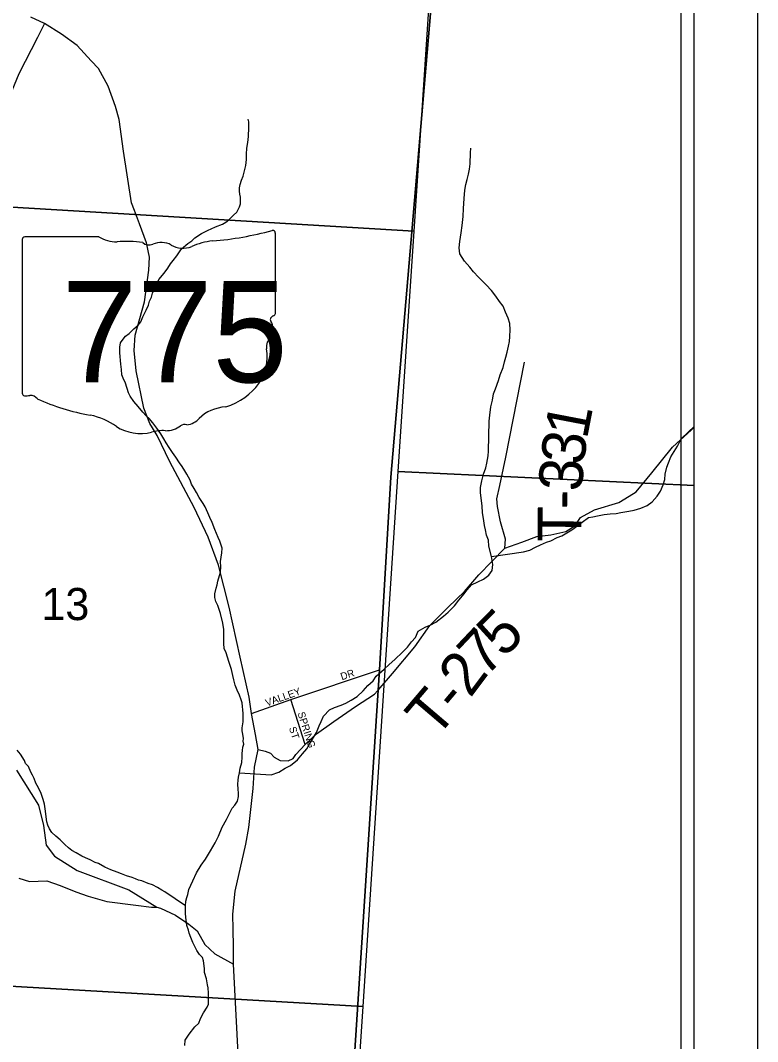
# Model space of a CAD drawing. Extents: x 0 to 34, y 0 to 22.
# Drawn here: x 8.54 to 9.5, y 17.764 to 19.094 of the extents above; entities that cross this region are included whole.
import ezdxf

# ---------------------------------------------------------------- set-up
doc = ezdxf.new("R2010")
doc.units = 0
for name, color, linetype in [('GM_X_County', 7, 'Continuous'), ('GM_X_Minor_River', 7, 'Continuous'), ('GM_X_Section', 7, 'Continuous'), ('GM_X_Section_Text', 7, 'Continuous'), ('GM_X_State_Location', 7, 'Continuous'), ('GM_X_State_Route', 7, 'Continuous'), ('GM_X_State_Shield', 7, 'Continuous'), ('GM_X_Township', 7, 'Continuous'), ('GM_X_Township_Road', 7, 'Continuous'), ('GM_X_Township_Road_Text', 7, 'Continuous'), ('GM_X_Township_ROW', 7, 'Continuous'), ('GM_X_Township_Subdivision', 7, 'Continuous'), ('GM_X_Township_Subdivision_Text', 7, 'Continuous'), ('SH_Data', 7, 'Continuous')]:
    doc.layers.add(name, color=color, linetype=linetype)

msp = doc.modelspace()

# ---------------------------------------------------------------- linework, layer by layer
at = {"layer": 'GM_X_County'}
msp.add_lwpolyline([(9.4175, 16.6203), (9.4175, 20.9), (2.6175, 20.9), (2.6175, 15.1694)], dxfattribs=at)
at = {"layer": 'GM_X_Minor_River'}
for points in [[(8.8024, 18.4004), (8.8025, 18.4064), (8.7996, 18.4156), (8.7974, 18.4202), (8.7931, 18.4305), (8.7898, 18.4397), (8.7865, 18.4462), (8.784, 18.4523), (8.7807, 18.46), (8.7781, 18.4646), (8.7726, 18.4723), (8.7693, 18.4788), (8.7664, 18.4841), (8.7627, 18.4899), (8.7609, 18.4949), (8.7568, 18.5029), (8.7539, 18.5071), (8.7506, 18.5129), (8.7473, 18.5175), (8.7425, 18.5248), (8.738, 18.531), (8.7336, 18.5375), (8.7299, 18.5436), (8.7266, 18.5486), (8.7229, 18.5551), (8.7178, 18.5628), (8.7126, 18.5697), (8.7077, 18.5751), (8.7036, 18.5786), (8.6996, 18.5836), (8.6933, 18.591), (8.6877, 18.5975), (8.6829, 18.6041), (8.6807, 18.6086), (8.6767, 18.6212), (8.6738, 18.6277), (8.672, 18.6323), (8.6718, 18.6392), (8.6707, 18.646), (8.6695, 18.6609), (8.6696, 18.6681), (8.6705, 18.6737), (8.6736, 18.6786), (8.6767, 18.6824), (8.6817, 18.6857), (8.6875, 18.6921), (8.6932, 18.6969), (8.6967, 18.701), (8.6995, 18.7078), (8.7038, 18.7165), (8.7066, 18.7229), (8.7082, 18.7282), (8.7105, 18.7334), (8.7121, 18.7384), (8.7153, 18.7463), (8.7204, 18.7561), (8.727, 18.7643), (8.732, 18.771), (8.7355, 18.7767), (8.7387, 18.7808), (8.7437, 18.7872), (8.7499, 18.7962), (8.758, 18.8029), (8.763, 18.8066), (8.7672, 18.8107), (8.7756, 18.8163), (8.7844, 18.8203), (8.7886, 18.8221), (8.794, 18.8247), (8.8031, 18.8283), (8.8073, 18.8309), (8.8112, 18.8339), (8.8173, 18.8398), (8.822, 18.8439), (8.8251, 18.8507), (8.8267, 18.8549), (8.8268, 18.859), (8.8265, 18.8636), (8.8258, 18.8674), (8.8255, 18.8712), (8.8255, 18.8754), (8.826, 18.8799), (8.828, 18.8856), (8.83, 18.8909), (8.8316, 18.8977), (8.8336, 18.9049), (8.8342, 18.9125), (8.8343, 18.9193), (8.8348, 18.9273), (8.8361, 18.9345), (8.8365, 18.9386), (8.837, 18.9424), (8.837, 18.9462), (8.8375, 18.9504), (8.8376, 18.9557), (8.8373, 18.9614), (8.8366, 18.9652)], [(9.1175, 18.8551), (9.118, 18.8619), (9.1189, 18.8726), (9.1202, 18.8801), (9.1218, 18.8866), (9.1234, 18.8934), (9.1247, 18.8998), (9.1259, 18.9067), (9.1262, 18.9211), (9.1266, 18.9272)], [(8.8254, 18.114), (8.8666, 18.1113), (8.8765, 18.1146), (8.8849, 18.1198), (8.8915, 18.1235), (8.9007, 18.1309), (8.9073, 18.1384), (8.9131, 18.1452), (8.9166, 18.1512), (8.9205, 18.1576), (8.9255, 18.1663), (8.9291, 18.175), (8.9315, 18.1807), (8.9346, 18.1875), (8.9427, 18.1957), (8.9489, 18.199), (8.9576, 18.2019), (8.9638, 18.2045), (8.9707, 18.2086), (8.9787, 18.2134), (8.9864, 18.2205), (8.9926, 18.2276), (8.9992, 18.2336), (9.0031, 18.2397), (9.0135, 18.2486), (9.02, 18.255), (9.0277, 18.2613), (9.0377, 18.2711), (9.0439, 18.2774), (9.0493, 18.2846), (9.0544, 18.2902), (9.0579, 18.2985), (9.0671, 18.3037), (9.0744, 18.3066), (9.0809, 18.31), (9.0909, 18.3178), (9.0971, 18.323), (9.1052, 18.3313), (9.111, 18.3388), (9.1179, 18.3467), (9.1218, 18.3523), (9.1276, 18.3587), (9.1357, 18.3627), (9.1429, 18.3661), (9.1502, 18.3713), (9.1545, 18.3773), (9.155, 18.3853), (9.1533, 18.3956), (9.1501, 18.4089), (9.1494, 18.4169), (9.1469, 18.4234), (9.1458, 18.4303), (9.1444, 18.436), (9.1434, 18.4421), (9.1416, 18.4528), (9.1414, 18.4611), (9.14, 18.4718), (9.139, 18.4783), (9.1391, 18.4855), (9.1411, 18.4942), (9.1432, 18.5026), (9.146, 18.5109), (9.1476, 18.517), (9.1492, 18.5264), (9.1497, 18.5329), (9.1503, 18.5717), (9.1512, 18.5796), (9.1525, 18.5903), (9.1546, 18.599), (9.1562, 18.6073), (9.1586, 18.6138), (9.1625, 18.6247), (9.1649, 18.6323), (9.1685, 18.6417), (9.1705, 18.6489), (9.1721, 18.655), (9.1738, 18.6614), (9.1754, 18.6694), (9.177, 18.6755), (9.1775, 18.6819), (9.178, 18.6906), (9.1774, 18.699), (9.1752, 18.7059), (9.1719, 18.7139), (9.1686, 18.7216), (9.1638, 18.7278), (9.159, 18.7347), (9.1534, 18.742), (9.1466, 18.7493), (9.1365, 18.7594), (9.1302, 18.7663), (9.1253, 18.7725), (9.1183, 18.7802), (9.1123, 18.7898), (9.1113, 18.7974), (9.1122, 18.8057), (9.1139, 18.8171), (9.1152, 18.8266), (9.1165, 18.8384), (9.117, 18.8486), (9.1175, 18.8551)], [(9.1533, 18.3956), (9.1952, 18.4014), (9.2032, 18.4039), (9.2108, 18.4076), (9.2173, 18.4105), (9.225, 18.4142), (9.2307, 18.416), (9.2391, 18.4201), (9.2449, 18.4223), (9.2579, 18.4301), (9.266, 18.436), (9.2717, 18.4401), (9.2798, 18.4461), (9.2855, 18.4472), (9.2916, 18.4486), (9.3, 18.45), (9.308, 18.451), (9.316, 18.4516), (9.3221, 18.4527), (9.3324, 18.4544), (9.3392, 18.4558), (9.348, 18.4584), (9.356, 18.462), (9.3626, 18.4669), (9.3691, 18.474), (9.3734, 18.4804), (9.377, 18.4887), (9.379, 18.4959), (9.3798, 18.5027), (9.3819, 18.5118), (9.3839, 18.5175), (9.387, 18.5251), (9.3956, 18.5394), (9.4007, 18.5488), (9.4103, 18.5582), (9.4165, 18.5638), (9.4175, 18.5645)], [(8.754, 17.7589), (8.7545, 17.7657), (8.7599, 17.7733), (8.7673, 17.783), (8.7723, 17.7879), (8.7743, 17.7939), (8.7786, 17.8014), (8.7832, 17.8086), (8.7848, 17.8127), (8.7851, 17.8271), (8.7844, 17.834), (8.7834, 17.8378), (8.7824, 17.8454), (8.7799, 17.8538), (8.7796, 17.8588), (8.7782, 17.8691), (8.7772, 17.8733), (8.7731, 17.8771), (8.7698, 17.8825), (8.7676, 17.8867), (8.7647, 17.8928), (8.7617, 17.8993), (8.7599, 17.9051), (8.7589, 17.9089), (8.7567, 17.915), (8.7554, 17.9257), (8.7551, 17.9306), (8.7548, 17.9359), (8.7549, 17.9405), (8.7554, 17.9466), (8.7566, 17.9515), (8.7582, 17.9552), (8.7594, 17.9617), (8.7645, 17.973), (8.7693, 17.9835), (8.7755, 17.9937), (8.781, 18.0012), (8.7876, 18.0121), (8.7938, 18.0226), (8.7978, 18.0313), (8.8025, 18.043), (8.8084, 18.0531), (8.8158, 18.0678), (8.8193, 18.0716), (8.8228, 18.0768), (8.8241, 18.0829), (8.8238, 18.0875), (8.8235, 18.0924), (8.8232, 18.0989), (8.8237, 18.1042), (8.8241, 18.1083), (8.8254, 18.114), (8.8262, 18.1197), (8.8282, 18.1273), (8.8287, 18.1341), (8.8288, 18.139), (8.8293, 18.1428), (8.8297, 18.1474), (8.8309, 18.1511), (8.8302, 18.1549), (8.8303, 18.1587), (8.8297, 18.1641), (8.8286, 18.1686), (8.8287, 18.1724), (8.8299, 18.1804), (8.8301, 18.191), (8.8289, 18.2051), (8.8274, 18.2089), (8.8252, 18.215), (8.8223, 18.2215), (8.8198, 18.228), (8.818, 18.2349), (8.8166, 18.2406), (8.8148, 18.2483), (8.8116, 18.2589), (8.808, 18.27), (8.8055, 18.2758), (8.8048, 18.2822), (8.805, 18.2929), (8.8048, 18.3005), (8.8034, 18.3088), (8.8006, 18.3214), (8.797, 18.3317), (8.7944, 18.3371), (8.793, 18.342), (8.7931, 18.347), (8.7947, 18.3542), (8.796, 18.3587), (8.7972, 18.3636), (8.8004, 18.375), (8.8009, 18.3822), (8.8007, 18.389), (8.8024, 18.4004)], [(8.7549, 17.9405), (8.7279, 17.9588), (8.7242, 17.9611), (8.7186, 17.9643), (8.7118, 17.9678), (8.7065, 17.9698), (8.6983, 17.973), (8.6937, 17.9742), (8.69, 17.9758), (8.6855, 17.9774), (8.6783, 17.9798), (8.6715, 17.9822), (8.6659, 17.9845), (8.6576, 17.9877), (8.6497, 17.9909), (8.6415, 17.9956), (8.6373, 17.9972), (8.6309, 18.0003), (8.6246, 18.0031), (8.62, 18.0055), (8.6125, 18.0098), (8.6069, 18.0125), (8.6028, 18.016), (8.5976, 18.0203), (8.5916, 18.0265), (8.586, 18.0315), (8.5808, 18.0361), (8.5779, 18.0407), (8.5757, 18.0457), (8.5742, 18.0499), (8.5736, 18.0564), (8.5729, 18.0606), (8.5723, 18.067), (8.5712, 18.0731), (8.5695, 18.0792), (8.5669, 18.0869), (8.5633, 18.0942), (8.56, 18.1003), (8.5578, 18.1064), (8.5556, 18.1106), (8.5534, 18.1145), (8.5505, 18.1221), (8.5464, 18.126), (8.5453, 18.1298), (8.5402, 18.1379), (8.5357, 18.1432)]]:
    msp.add_lwpolyline(points, dxfattribs=at)
at = {"layer": 'GM_X_Section'}
for p, q in [((9.4175, 18.4879), (9.4175, 19.5279)), ((9.4175, 17.4574), (9.4175, 18.4879))]:
    msp.add_line(p, q, dxfattribs=at)
for points in [[(8.0453, 19.8934), (9.1186, 19.8297), (9.0999, 19.5424), (9.0522, 18.819), (7.9764, 18.8836)], [(7.9764, 18.8836), (9.0522, 18.819), (9.0316, 18.5064), (8.9857, 17.8095), (7.9078, 17.8715)], [(7.9078, 17.8715), (8.9857, 17.8095), (8.9637, 17.4779), (8.9185, 16.8056), (7.8396, 16.8632)]]:
    msp.add_lwpolyline(points, close=True, dxfattribs=at)
for points in [[(9.4175, 19.5279), (9.0999, 19.5424), (9.0522, 18.819), (9.0316, 18.5064), (9.4175, 18.4879)], [(9.4175, 18.4879), (9.0316, 18.5064), (8.9857, 17.8095), (8.9637, 17.4779), (9.1355, 17.47), (9.3154, 17.462), (9.4175, 17.4574)]]:
    msp.add_lwpolyline(points, dxfattribs=at)
at = {"layer": 'GM_X_State_Route'}
for points in [[(8.6885, 18.8462), (8.6848, 18.8562), (8.6744, 18.9234), (8.6685, 18.9644), (8.6637, 18.9815), (8.6541, 19.0078), (8.6418, 19.0308), (8.6321, 19.0412), (8.614, 19.061), (8.5934, 19.0759), (8.5713, 19.0895), (8.5535, 19.0977)], [(8.718, 18.553), (8.7168, 18.5554), (8.7084, 18.5689), (8.7005, 18.5888), (8.6907, 18.6372), (8.6883, 18.6638), (8.6895, 18.6839), (8.7015, 18.7272), (8.707, 18.7684), (8.7082, 18.7855), (8.7041, 18.8038), (8.695, 18.8286), (8.6885, 18.8462)], [(8.83, 17.6237), (8.8173, 17.8647), (8.8175, 17.8878), (8.8169, 17.9098), (8.8166, 17.9299), (8.8196, 17.9599), (8.8335, 18.021), (8.8375, 18.0425), (8.8432, 18.0936), (8.845, 18.1213), (8.8495, 18.144), (8.846, 18.1639), (8.8411, 18.1912), (8.8377, 18.2125), (8.826, 18.2644), (8.812, 18.3296), (8.7981, 18.3842), (8.7845, 18.4206), (8.7661, 18.4593), (8.7345, 18.5189), (8.718, 18.553)]]:
    msp.add_lwpolyline(points, dxfattribs=at)
at = {"layer": 'GM_X_State_Shield'}
for p, q in [((8.872, 18.7121), (8.872, 18.8168)), ((8.5424, 18.8084), (8.5424, 18.6082)), ((8.6422, 18.8118), (8.5456, 18.8118)), ((8.8719, 18.7121), (8.872, 18.7121))]:
    msp.add_line(p, q, dxfattribs=at)
for centre, major_axis, start_param, end_param in [((8.7546, 19.0846), (0.3495, 0), 4.814394, 5.042369), ((8.8683, 18.8172), (0.00367, 0), 6.141152, 7.989035), ((8.5462, 18.8088), (0.00382, 0), 1.712693, 3.28349), ((8.6651, 18.835), (0.037, 0), 4.042523, 4.731795), ((8.6774, 18.6995), (0.133, 0), 1.404758, 1.657858), ((8.7076, 18.8098), (0.0107, 0), 3.836095, 5.185415), ((8.7233, 18.7867), (0.0222, 0), 0.950623, 2.079405), ((8.7991, 18.7507), (0.0703, 0), 1.699011, 2.107814), ((8.752, 18.8184), (0.0267, 0), 4.081561, 5.145723), ((8.8681, 18.7117), (0.00393, 0), 5.05454, 6.418171), ((8.8711, 18.7044), (0.00568, 0), 1.883978, 3.671073), ((8.835, 18.6912), (0.0341, 0), 5.934695, 6.695948), ((8.8851, 18.6683), (0.0248, 0), 2.387724, 3.262537), ((8.7741, 18.6549), (0.0874, 0), 5.101752, 6.440018), ((8.5462, 18.6078), (0.00385, 0), 3.00124, 4.508301), ((8.5468, 18.6283), (0.0294, 0), 4.665946, 4.897461), ((8.5528, 18.5967), (0.0106, 0), 0.519207, 1.627899), ((8.6866, 18.7765), (0.2524, 0), 4.195997, 4.488961), ((8.811, 18.5521), (0.0479, 0), 1.647645, 2.488434), ((8.6114, 18.5183), (0.079, 0), 0.823519, 1.323587), ((8.6968, 18.5957), (0.0501, 0), 4.026481, 4.996735), ((8.7294, 18.5807), (0.0267, 0), 4.691044, 5.507374), ((8.7536, 18.5613), (0.00752, 0), 1.147584, 2.315152), ((8.7503, 18.5888), (0.0282, 0), 4.937069, 5.64225), ((8.7257, 18.5265), (0.0412, 0), 1.495662, 1.94098)]:
    msp.add_ellipse(centre, major_axis=major_axis, ratio=0.8, start_param=start_param, end_param=end_param, dxfattribs=at)
at = {"layer": 'GM_X_Township'}
for points in [[(9.4175, 16.6203), (9.4175, 20.9), (9.195, 20.9)], [(8.6432, 16.4316), (8.683, 16.4407), (8.7669, 16.4493), (8.8556, 16.4772), (8.8923, 16.484), (8.901, 16.6186), (8.9012, 16.6208), (8.9166, 16.8597), (8.9362, 17.0179), (8.9323, 17.0798), (8.935, 17.1194), (8.9411, 17.1683), (8.943, 17.2389), (8.9475, 17.3122), (8.9502, 17.3554), (8.9552, 17.4373), (9.0057, 18.2215), (9.0074, 18.2481), (9.0224, 18.4988), (9.0811, 19.1844)], [(9.0811, 19.1844), (9.0224, 18.4988), (9.0074, 18.2481), (9.0057, 18.2215), (8.9552, 17.4373), (8.9502, 17.3554), (8.9475, 17.3122), (8.943, 17.2389), (8.9411, 17.1683), (8.935, 17.1194), (8.9323, 17.0798), (8.9362, 17.0179), (8.9166, 16.8597), (8.9012, 16.6208), (8.901, 16.6186), (8.8923, 16.484), (8.9618, 16.497), (9.0399, 16.5227), (9.1499, 16.5553), (9.1984, 16.5652), (9.2446, 16.5735), (9.3091, 16.5958), (9.3588, 16.611), (9.4175, 16.6203)]]:
    msp.add_lwpolyline(points, dxfattribs=at)
at = {"layer": 'GM_X_Township_Road'}
for points in [[(8.5713, 19.0895), (8.5624, 19.0712), (8.538, 19.0241), (8.5227, 18.987), (8.512, 18.9559), (8.4961, 18.8946), (8.4928, 18.876)], [(9.1708, 18.4065), (9.1718, 18.418), (9.1653, 18.4408), (9.1612, 18.4605), (9.1604, 18.4707), (9.1642, 18.4878), (9.1721, 18.525), (9.1963, 18.6487)], [(9.1708, 18.4065), (9.1929, 18.414), (9.2124, 18.4216), (9.2307, 18.4237), (9.2501, 18.428), (9.262, 18.4356), (9.2695, 18.4464), (9.2878, 18.4561), (9.3191, 18.4658), (9.3382, 18.4776), (9.3418, 18.4798), (9.3623, 18.5046), (9.3892, 18.538), (9.3945, 18.5428)], [(9.0049, 18.2207), (9.0057, 18.2215), (9.0247, 18.2432), (9.0538, 18.2777), (9.0732, 18.3057), (9.097, 18.3294), (9.1185, 18.3499), (9.1369, 18.3715), (9.1708, 18.4065)], [(8.9197, 18.1589), (8.92, 18.1592), (8.9255, 18.1645), (8.9481, 18.1806), (8.9762, 18.2), (9.001, 18.2162), (9.0049, 18.2207)], [(8.8495, 18.144), (8.8585, 18.1422), (8.8656, 18.1393), (8.8705, 18.1343), (8.8783, 18.13), (8.8886, 18.1295), (8.895, 18.1323), (8.8985, 18.1375), (8.9109, 18.1505), (8.9197, 18.1589)], [(8.5347, 18.1172), (8.5637, 18.0718), (8.5702, 18.0453), (8.5736, 18.0198), (8.5843, 18.0051), (8.6139, 17.9865), (8.6811, 17.9613), (8.7175, 17.939)], [(8.5379, 17.9768), (8.5518, 17.9724), (8.5745, 17.9732), (8.5916, 17.9671), (8.6121, 17.9588), (8.628, 17.9532), (8.6523, 17.9464), (8.6902, 17.9416), (8.7107, 17.9389), (8.7175, 17.939), (8.7225, 17.9374), (8.7418, 17.9284), (8.7592, 17.9167), (8.7703, 17.9079), (8.7802, 17.8901), (8.7931, 17.878), (8.8173, 17.8647)]]:
    msp.add_lwpolyline(points, dxfattribs=at)
at = {"layer": 'GM_X_Township_ROW'}
msp.add_lwpolyline([(9.3945, 18.5428), (9.414, 18.5606), (9.4175, 18.5644)], dxfattribs=at)
at = {"layer": 'GM_X_Township_Subdivision'}
for points in [[(8.8411, 18.1912), (8.8922, 18.2094), (9.0074, 18.2481)], [(8.9109, 18.1505), (8.8922, 18.2094)]]:
    msp.add_lwpolyline(points, dxfattribs=at)
at = {"layer": 'SH_Data'}
for p, q in [((9.5, 21), (9.5, 14)), ((9.4, 20.9), (9.4, 14.1))]:
    msp.add_line(p, q, dxfattribs=at)

# ---------------------------------------------------------------- texts
at = {"layer": 'GM_X_Section_Text'}
msp.add_text('13', height=0.04186, rotation=0, dxfattribs=at).set_placement((8.5674, 18.3127))
at = {"layer": 'GM_X_State_Location'}
for s in ['s', 'r']:
    msp.add_text(s, height=0.000189, dxfattribs=at).set_placement((8.7035, 18.695))
msp.add_text('775', height=0.000189, rotation=0, dxfattribs=at).set_placement((8.6366, 18.6812))
at = {"layer": 'GM_X_State_Shield'}
msp.add_text('775', height=0.13184, dxfattribs=at).set_placement((8.5939, 18.6224))
at = {"layer": 'GM_X_Township_Road_Text'}
for s, rotation, p in [('1', 79.1526, (9.2777, 18.5471)), ('3', 82.7944, (9.2735, 18.5133)), ('3', 86.1149, (9.2712, 18.4793)), ('-', 88.5636, (9.2706, 18.4566)), ('T', 89.46, (9.2702, 18.4143)), ('5', 45.5506, (9.1695, 18.2622)), ('7', 46.5913, (9.1456, 18.237)), ('2', 53.2511, (9.1258, 18.2103)), ('T', 49.5816, (9.0808, 18.1569)), ('-', 50.0614, (9.1087, 18.1897))]:
    msp.add_text(s, height=0.0568, rotation=rotation, dxfattribs=at).set_placement(p)
at = {"layer": 'GM_X_Township_Subdivision_Text'}
for s, rotation, p in [('DR', 18.4372, (8.9586, 18.2343)), ('VALLEY', 19.722, (8.861, 18.2001)), ('SPRING', 287.6998, (8.9008, 18.1915)), ('ST', 288.4382, (8.8895, 18.1722))]:
    msp.add_text(s, height=0.00947, rotation=rotation, dxfattribs=at).set_placement(p)

doc.saveas('drawing.dxf')
